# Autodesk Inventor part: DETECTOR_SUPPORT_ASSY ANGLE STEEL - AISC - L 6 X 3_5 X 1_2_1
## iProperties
Shininess: 64.0
Length Units: 11272
Angle Units: 11279
Time Units: 11290
Mass Units: 11286
Length Display Precision: 3
Angle Display Precision: 2
Compacted: True
Part Number: DETECTOR_SUPPORT_ASSY ANGLE STEEL - AISC - L 6 X 3_5 X 1_2_1
Document SubType Name: Modeling
Created: 2004-08
Designer: John Blackburn
Material: MILD_STEEL
Manufacturer: Standard
Standards Organization: Custom
Density: 0.0
Volumn: 0.0
Area: 0.0
PropertySet Name: Model Information
Control State: 0
Master: False
Checked Out: False
Author: John Blackburn
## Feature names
1. BaseExt [Extrusion]
2. ThrghExt_1 [Extrusion]
3. ExtrusionThru1
